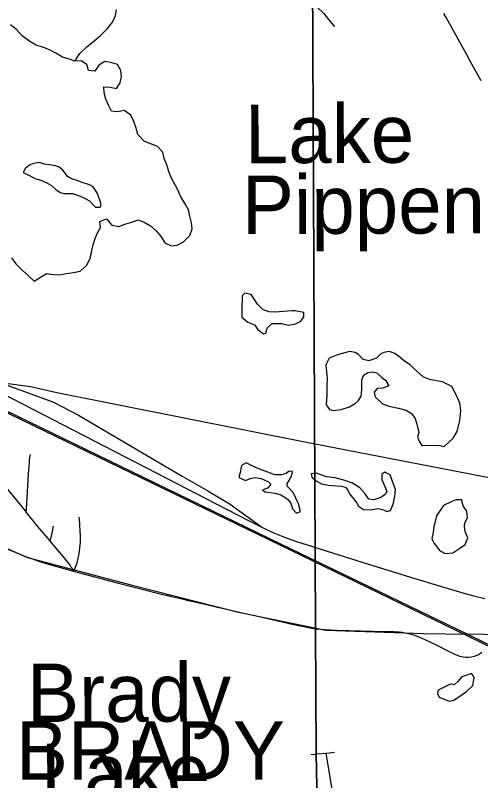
# Model space of a CAD drawing. Extents: x 0 to 34, y 0 to 22.
# Drawn here: x 4.562 to 5.317, y 14.44 to 15.681 of the extents above; entities that cross this region are included whole.
import ezdxf

# ---------------------------------------------------------------- set-up
doc = ezdxf.new("R2010")
doc.units = 0
for name, color, linetype in [('GM_X_Corporation', 7, 'Continuous'), ('GM_X_Corporation_Text', 7, 'Continuous'), ('GM_X_County_Road', 7, 'Continuous'), ('GM_X_Major_Lake', 7, 'Continuous'), ('GM_X_Major_Lake_Text', 7, 'Continuous'), ('GM_X_Minor_Lake', 7, 'Continuous'), ('GM_X_Minor_River', 7, 'Continuous'), ('GM_X_Rail_Line', 7, 'Continuous'), ('GM_X_Township_Road', 7, 'Continuous')]:
    doc.layers.add(name, color=color, linetype=linetype)

msp = doc.modelspace()

# ---------------------------------------------------------------- linework, layer by layer
at = {"layer": 'GM_X_Corporation'}
for points in [[(2.114, 13.8173), (5.0539, 13.8173), (5.0552, 14.1423), (5.0521, 14.2095), (5.0518, 14.2807), (5.0535, 14.3223), (5.0506, 14.4841), (5.0493, 14.6873), (5.0428, 16.1022), (5.0398, 16.4459), (5.0375, 17.2161), (5.0375, 17.2177), (5.0364, 17.2177), (4.9837, 17.2182), (4.8829, 17.219), (4.8603, 17.2191), (4.8453, 17.219), (4.8174, 17.2186), (4.7998, 17.2177), (4.7904, 17.2169), (4.7848, 17.216), (4.7806, 17.215), (4.732, 17.2135), (3.7259, 17.2107)], [(5.0428, 16.1022), (5.0493, 14.6873), (5.0506, 14.4841), (5.0535, 14.3223), (5.0518, 14.2807), (5.0521, 14.2095), (5.0552, 14.1423), (5.0539, 13.8173), (8.914, 13.8173)]]:
    msp.add_lwpolyline(points, dxfattribs=at)
at = {"layer": 'GM_X_County_Road'}
for points in [[(5.3182, 15.5753), (5.3128, 15.5847), (5.3057, 15.5971), (5.3003, 15.6068), (5.294, 15.6182), (5.2866, 15.6319), (5.2773, 15.6486), (5.261, 15.6776), (5.2575, 15.6842)], [(4.4791, 14.9956), (4.4934, 14.978), (4.5085, 14.9608), (4.5274, 14.9385), (4.5359, 14.9287), (4.5782, 14.8777), (4.5802, 14.8753)], [(4.5802, 14.8753), (4.598, 14.853), (4.6149, 14.8331), (4.6191, 14.8281)], [(4.6191, 14.8281), (4.634, 14.8102), (4.6422, 14.8008), (4.6485, 14.7926), (4.6512, 14.789), (4.6526, 14.7871), (4.6539, 14.7852), (4.6566, 14.7801)], [(4.5488, 14.8164), (4.561, 14.8112), (4.5724, 14.8065), (4.5807, 14.8032), (4.5842, 14.8019), (4.603, 14.7953), (4.6197, 14.7902), (4.6566, 14.7801)], [(4.6566, 14.7801), (4.6664, 14.7774), (4.7276, 14.7611), (4.7571, 14.7536), (4.7908, 14.7448), (4.804, 14.7416), (4.8076, 14.7409), (4.813, 14.7396), (4.8323, 14.7351), (4.8372, 14.734), (4.8401, 14.7332), (4.8509, 14.7307), (4.8679, 14.7268), (4.8903, 14.7217), (4.9097, 14.7172), (4.9187, 14.7151), (4.9351, 14.7115), (4.9605, 14.7057), (4.9835, 14.7004), (4.995, 14.6977), (5.0089, 14.6945), (5.0144, 14.6934), (5.0216, 14.6918), (5.0277, 14.6906), (5.0435, 14.6876), (5.0495, 14.6867)], [(5.0495, 14.6867), (5.0515, 14.6864), (5.0644, 14.6852), (5.0839, 14.6844), (5.1228, 14.6835), (5.162, 14.6824), (5.1763, 14.6821), (5.1851, 14.6815), (5.1901, 14.6809), (5.1943, 14.6802), (5.2004, 14.6789), (5.2083, 14.6766), (5.217, 14.6733), (5.2268, 14.6691), (5.2381, 14.6639), (5.2448, 14.6606), (5.2648, 14.6505), (5.2765, 14.645), (5.2834, 14.6424), (5.2887, 14.641), (5.2929, 14.6404), (5.2972, 14.6403), (5.3026, 14.6409), (5.3073, 14.6421), (5.3118, 14.6439), (5.3139, 14.6449), (5.3167, 14.6468), (5.3193, 14.6488)]]:
    msp.add_lwpolyline(points, dxfattribs=at)
at = {"layer": 'GM_X_Major_Lake'}
msp.add_line((4.6274, 15.4372), (4.618, 15.4387), dxfattribs=at)
for points in [[(4.815, 15.3075), (4.8249, 15.3087), (4.835, 15.3141), (4.8456, 15.3244), (4.8493, 15.3351), (4.848, 15.3449), (4.8457, 15.3555), (4.843, 15.3657), (4.8376, 15.3759), (4.8303, 15.388), (4.8257, 15.3986), (4.8149, 15.4182), (4.8114, 15.4281), (4.8083, 15.4387), (4.8037, 15.4492), (4.8014, 15.4595), (4.7926, 15.4693), (4.7816, 15.473), (4.7713, 15.4774), (4.761, 15.4883), (4.7583, 15.4986), (4.7544, 15.5092), (4.7498, 15.5194), (4.7387, 15.5272), (4.7282, 15.5249), (4.7183, 15.5259), (4.7133, 15.5358), (4.7091, 15.5456), (4.7064, 15.5558), (4.7059, 15.5653), (4.7161, 15.565), (4.7267, 15.5624), (4.7323, 15.5719), (4.7345, 15.5822), (4.7333, 15.592), (4.7279, 15.6018), (4.7173, 15.6048), (4.7078, 15.6066), (4.6977, 15.6005), (4.6913, 15.5909), (4.6811, 15.592), (4.6784, 15.6018), (4.6689, 15.6075), (4.659, 15.607), (4.6495, 15.61), (4.6389, 15.6137), (4.6283, 15.62), (4.6176, 15.6256), (4.6078, 15.629), (4.596, 15.6327), (4.5861, 15.639), (4.5735, 15.648), (4.564, 15.6582), (4.5545, 15.6661)], [(4.618, 15.4387), (4.6096, 15.4398), (4.6016, 15.4427), (4.5918, 15.4411), (4.5865, 15.4388), (4.5786, 15.4335), (4.5749, 15.4266), (4.584, 15.4221), (4.5939, 15.4165), (4.6038, 15.4139), (4.6133, 15.4098), (4.6209, 15.4053), (4.6281, 15.399), (4.635, 15.3941), (4.6422, 15.3926), (4.655, 15.3923), (4.6664, 15.3886), (4.6759, 15.3845), (4.6827, 15.3804), (4.6873, 15.3751), (4.6923, 15.3703), (4.7002, 15.3703), (4.7017, 15.3745), (4.7002, 15.3802), (4.6975, 15.3877), (4.6951, 15.3934), (4.6886, 15.4032), (4.6825, 15.4066), (4.6693, 15.411), (4.6624, 15.4136), (4.6533, 15.4162), (4.6472, 15.42), (4.643, 15.4252), (4.6392, 15.4301), (4.6335, 15.435), (4.6274, 15.4372)], [(4.5559, 15.288), (4.5632, 15.2782), (4.5735, 15.2681), (4.583, 15.2594), (4.5929, 15.2504), (4.6031, 15.2566), (4.6136, 15.2627), (4.6239, 15.2613), (4.6337, 15.2606), (4.6454, 15.2626), (4.6568, 15.2642), (4.6677, 15.2665), (4.6779, 15.2757), (4.6839, 15.2871), (4.6857, 15.2974), (4.6882, 15.3073), (4.6912, 15.3179), (4.6953, 15.3278), (4.7005, 15.3373), (4.6993, 15.3472), (4.7102, 15.3511), (4.719, 15.3413), (4.7304, 15.3391), (4.7402, 15.3429), (4.7511, 15.3457), (4.7617, 15.3496), (4.7712, 15.3458), (4.7815, 15.3402), (4.791, 15.332), (4.799, 15.3222), (4.8048, 15.3124), (4.815, 15.3075)]]:
    msp.add_lwpolyline(points, dxfattribs=at)
at = {"layer": 'GM_X_Minor_Lake'}
for p, q in [((5.0115, 15.2021), (4.9835, 15.2)), ((5.2136, 15.0186), (5.2167, 15.0046)), ((4.9833, 14.936), (4.9522, 14.9479)), ((5.1047, 14.9055), (5.1158, 14.8912)), ((5.2436, 14.8603), (5.2414, 14.8524)), ((5.2664, 14.5962), (5.248, 14.5873))]:
    msp.add_line(p, q, dxfattribs=at)
for points in [[(4.9835, 15.2), (4.9741, 15.2007), (4.9642, 15.204), (4.9551, 15.213), (4.9501, 15.2206), (4.9447, 15.2285), (4.9349, 15.2307), (4.9303, 15.2265), (4.9298, 15.2037), (4.9299, 15.192), (4.9394, 15.1837), (4.9504, 15.1792), (4.9558, 15.1717), (4.9649, 15.1646), (4.9687, 15.1657), (4.9709, 15.1741), (4.9784, 15.1814), (4.9939, 15.1815), (5.0053, 15.1789), (5.0166, 15.1813), (5.0253, 15.1855), (5.0302, 15.1924), (5.0305, 15.1992), (5.0165, 15.2021), (5.0115, 15.2021)], [(5.2167, 15.0046), (5.2149, 14.9974), (5.2176, 14.9906), (5.2218, 14.9838), (5.2335, 14.9843), (5.2506, 14.984), (5.2578, 14.9822), (5.2724, 14.9959), (5.2791, 15.0066), (5.2835, 15.0241), (5.2849, 15.0404), (5.2833, 15.0525), (5.2779, 15.065), (5.2702, 15.0794), (5.2554, 15.0872), (5.2365, 15.0905), (5.2247, 15.0945), (5.2095, 15.1081), (5.2026, 15.1145), (5.1939, 15.1205), (5.1866, 15.1265), (5.1779, 15.1329), (5.1695, 15.1362), (5.1604, 15.1346), (5.1555, 15.1323), (5.1484, 15.1254), (5.1356, 15.1208), (5.1265, 15.1234), (5.1192, 15.1313), (5.1135, 15.1346), (5.1044, 15.1361), (5.0851, 15.131), (5.0716, 15.1256), (5.066, 15.1145), (5.068, 15.0929), (5.0674, 15.0812), (5.0675, 15.066), (5.0665, 15.0497), (5.0718, 15.0422), (5.0779, 15.0403), (5.0911, 15.0423), (5.1047, 15.0466), (5.1141, 15.0524), (5.119, 15.0569), (5.1235, 15.0638), (5.1246, 15.0748), (5.1245, 15.0816), (5.1245, 15.0896), (5.1263, 15.0949), (5.1293, 15.0991), (5.1342, 15.1022), (5.141, 15.103), (5.149, 15.1015), (5.1573, 15.0936), (5.1627, 15.0895), (5.1684, 15.0805), (5.1586, 15.0766), (5.1492, 15.0761), (5.1447, 15.0704), (5.1459, 15.0628), (5.1577, 15.0516), (5.1683, 15.0478), (5.1838, 15.0442), (5.1964, 15.0412), (5.2051, 15.0356), (5.2109, 15.0273), (5.2136, 15.0186)], [(4.9522, 14.9479), (4.9465, 14.9509), (4.937, 14.9554), (4.9291, 14.9516), (4.9287, 14.9489), (4.9269, 14.9402), (4.9247, 14.9318), (4.9357, 14.927), (4.9433, 14.9304), (4.9516, 14.932), (4.9614, 14.9302), (4.9728, 14.925), (4.9766, 14.9212), (4.9725, 14.9151), (4.9635, 14.9116), (4.9676, 14.9086), (4.9839, 14.9065), (4.993, 14.9039), (4.9999, 14.8994), (5.0045, 14.8964), (5.0091, 14.89), (5.0118, 14.8813), (5.0183, 14.8741), (5.0247, 14.8765), (5.0215, 14.8893), (5.0131, 14.9075), (5.0032, 14.9176), (5.0031, 14.9222), (5.0065, 14.9271), (5.0084, 14.9309), (5.0106, 14.9336), (5.0113, 14.9378), (5.0121, 14.9416), (5.0064, 14.9419), (5.0015, 14.9385), (4.9943, 14.9361), (4.9898, 14.9361), (4.9833, 14.936)], [(5.1158, 14.8912), (5.1192, 14.8852), (5.1272, 14.8799), (5.1378, 14.8792), (5.1507, 14.8816), (5.1598, 14.8794), (5.1651, 14.8768), (5.1711, 14.8784), (5.1752, 14.8886), (5.1782, 14.9012), (5.1792, 14.9125), (5.1761, 14.9197), (5.1703, 14.936), (5.1616, 14.9408), (5.1567, 14.9374), (5.1571, 14.9287), (5.1617, 14.9173), (5.1648, 14.909), (5.1622, 14.9041), (5.1551, 14.8995), (5.1438, 14.8956), (5.1358, 14.897), (5.1293, 14.9057), (5.1213, 14.9151), (5.1095, 14.9226), (5.0954, 14.9278), (5.0814, 14.9315), (5.067, 14.9329), (5.0598, 14.9359), (5.0503, 14.9388), (5.042, 14.9376), (5.0432, 14.9323), (5.0504, 14.9267), (5.0591, 14.9218), (5.0701, 14.9193), (5.077, 14.919), (5.0913, 14.9176), (5.0978, 14.9161), (5.1016, 14.9116), (5.1047, 14.9055)], [(5.2414, 14.8524), (5.2399, 14.8425), (5.2381, 14.8322), (5.2416, 14.8251), (5.2469, 14.819), (5.2507, 14.8134), (5.2595, 14.8085), (5.272, 14.8097), (5.2833, 14.8174), (5.2919, 14.8232), (5.2964, 14.8338), (5.2921, 14.8444), (5.2909, 14.8527), (5.2913, 14.8584), (5.2958, 14.8664), (5.2949, 14.8774), (5.2896, 14.8846), (5.2876, 14.8895), (5.2868, 14.8959), (5.2777, 14.8959), (5.2691, 14.8924), (5.257, 14.8866), (5.2458, 14.8695), (5.2436, 14.8603)], [(5.248, 14.5873), (5.2473, 14.5816), (5.2499, 14.5756), (5.2591, 14.5719), (5.2666, 14.5693), (5.2735, 14.5708), (5.2874, 14.58), (5.2942, 14.585), (5.3043, 14.5946), (5.3058, 14.601), (5.3065, 14.6064), (5.3046, 14.6113), (5.3026, 14.6139), (5.2962, 14.612), (5.2868, 14.6085), (5.2804, 14.6012), (5.274, 14.5959), (5.2702, 14.597), (5.2664, 14.5962)]]:
    msp.add_lwpolyline(points, dxfattribs=at)
at = {"layer": 'GM_X_Minor_River'}
for points in [[(4.9785, 15.7957), (4.9908, 15.7753), (4.9977, 15.7651), (4.9985, 15.7552), (5.0061, 15.7454), (5.0164, 15.7357), (5.0256, 15.7255), (5.0363, 15.7153), (5.0435, 15.7048), (5.0516, 15.695), (5.0626, 15.6845), (5.0703, 15.6747), (5.0791, 15.6645), (5.0791, 15.6626)], [(4.659, 15.607), (4.6672, 15.6196), (4.6785, 15.6303), (4.6902, 15.6399), (4.7007, 15.6487), (4.712, 15.6601), (4.7198, 15.67), (4.7247, 15.6811), (4.7265, 15.6906)]]:
    msp.add_lwpolyline(points, dxfattribs=at)
at = {"layer": 'GM_X_Rail_Line'}
for points in [[(6.8257, 13.9299), (6.7419, 13.9706), (6.3738, 14.1502), (6.2876, 14.192), (5.697, 14.4804), (5.3198, 14.6635), (5.2954, 14.6752), (4.9919, 14.8219), (4.4345, 15.0918)], [(6.8268, 13.932), (6.743, 13.9727), (6.3748, 14.1523), (6.2886, 14.1941), (5.698, 14.4825), (5.3208, 14.6656), (5.2965, 14.6773), (4.993, 14.824), (4.4354, 15.094)], [(4.5328, 15.0878), (4.5386, 15.0852), (4.6242, 15.0539), (4.6649, 15.0332), (4.8329, 14.9343), (4.8746, 14.9101), (4.9111, 14.8885), (4.9361, 14.8704), (4.9618, 14.8519)], [(4.551, 15.0845), (4.5877, 15.0793), (4.6298, 15.0695), (5.0347, 14.9892), (5.3505, 14.928), (5.482, 14.9083), (5.5377, 14.9006), (5.5871, 14.8954), (5.6352, 14.8931), (5.6764, 14.8939), (5.718, 14.8975), (5.7714, 14.9056), (5.8163, 14.9137), (5.9167, 14.9242), (6.0732, 14.9436), (6.2567, 14.9742), (6.4552, 14.9985)], [(4.5402, 15.0685), (4.8074, 14.9306), (4.9395, 14.8625), (4.962, 14.8514), (4.9801, 14.8425), (4.9991, 14.8349), (5.0152, 14.829), (5.0581, 14.8156), (5.1353, 14.7916), (5.2032, 14.7702), (5.2538, 14.7551), (5.2899, 14.7441), (5.3061, 14.7399), (5.324, 14.7358)], [(3.1757, 14.5864), (3.6056, 14.777), (3.709, 14.8243), (3.8008, 14.858), (3.9746, 14.9077), (4.0254, 14.9101), (4.301, 14.9178), (4.3473, 14.9048), (4.5823, 14.8024), (4.7517, 14.7573), (4.9245, 14.7137), (5.0662, 14.6846), (5.2252, 14.6792), (5.2963, 14.6779)], [(7.8047, 13.8173), (7.8032, 13.8784), (7.8061, 14.0853), (7.8056, 14.1774), (7.691, 14.1788), (7.619, 14.1835), (7.5106, 14.1906), (7.0652, 14.2059), (6.6818, 14.2193), (6.4657, 14.226), (6.0658, 14.6509), (5.3757, 14.6762), (5.2963, 14.6779)]]:
    msp.add_lwpolyline(points, dxfattribs=at)
at = {"layer": 'GM_X_Township_Road'}
for points in [[(4.5802, 14.8753), (4.5806, 14.8807), (4.5829, 14.9182), (4.5838, 14.9372), (4.5847, 14.9508), (4.5851, 14.9553), (4.5855, 14.9594), (4.5861, 14.9642), (4.5866, 14.9667), (4.5872, 14.9691)], [(4.6566, 14.7801), (4.6592, 14.785), (4.6606, 14.7881), (4.6619, 14.7917), (4.6638, 14.7984), (4.6655, 14.8057), (4.6666, 14.8121), (4.6672, 14.8182), (4.6679, 14.8265), (4.6679, 14.837), (4.6676, 14.8457), (4.6672, 14.8537), (4.667, 14.8574), (4.6659, 14.8676)], [(4.6191, 14.8281), (4.6219, 14.8416), (4.6243, 14.8529)], [(5.0423, 14.4825), (5.0491, 14.4833), (5.0508, 14.4835), (5.0518, 14.4836)], [(5.0518, 14.4836), (5.0666, 14.485), (5.0677, 14.4851), (5.0801, 14.4864)], [(5.0833, 14.3834), (5.0713, 14.4557), (5.0666, 14.485)]]:
    msp.add_lwpolyline(points, dxfattribs=at)

# ---------------------------------------------------------------- texts
at = {"layer": 'GM_X_Corporation_Text'}
msp.add_text('BRADY', height=0.0947, rotation=0, dxfattribs=at).set_placement((4.5633, 14.4419))
at = {"layer": 'GM_X_Major_Lake_Text'}
for s, height, rotation, p in [('Lake', 0.09474, 0.1754, (4.9348, 15.4414)), ('Pippen', 0.09474, 0.175, (4.93, 15.3266)), ('Brady', 0.09475, 0.1785, (4.5814, 14.5352)), ('Lake', 0.09475, 0.1792, (4.6038, 14.4053))]:
    msp.add_text(s, height=height, rotation=rotation, dxfattribs=at).set_placement(p)

doc.saveas('drawing.dxf')
